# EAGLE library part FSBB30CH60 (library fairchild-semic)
Smart Power Module 600V-30A IGBT inverter for three-phase DC/AC power conversion Source: http://www.fairchildsemi.com/ds/FS/FSBB30CH60.pdf
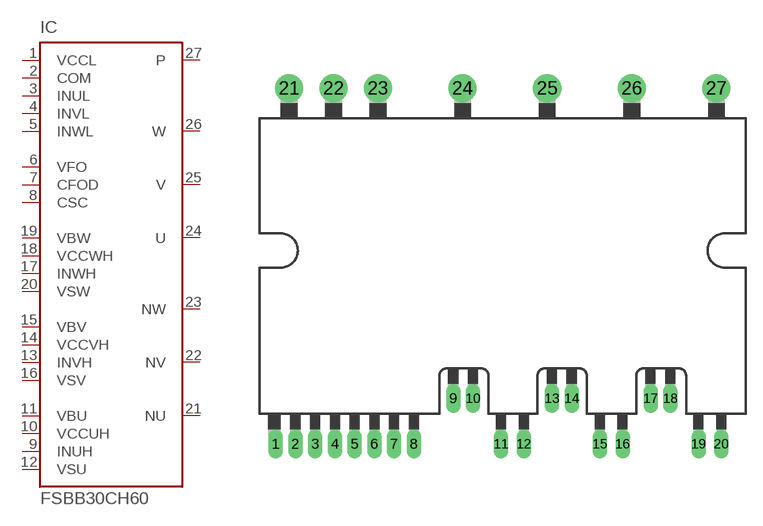
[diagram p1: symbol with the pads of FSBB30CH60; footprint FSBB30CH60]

Designator prefix IC

## FSBB30CH60 (MPN: FSBB30CH60B; OC_FARNELL: 1783234; OC_NEWARK: 78M1076)  [FSBB30CH60]
1  VCCL  pwr
2  COM  pwr
3  INUL  in
4  INVL  in
5  INWL  in
6  VFO  out
7  CFOD  pas
8  CSC  pas
9  INUH  in
10  VCCUH  in
11  VBU  in
12  VSU  in
13  INVH  in
14  VCCVH  in
15  VBV  in
16  VSV  in
17  INWH  in
18  VCCWH  in
19  VBW  in
20  VSW  in
21  NU  in
22  NV  in
23  NW  in
24  U  out
25  V  out
26  W  out
27  P  in

## Footprint FSBB30CH60 (pad centres in mm)
SPM27-EA UL Certified No.E209204 Source: http://www.fairchildsemi.com/ds/FS/FSBB30CH60.pdf
drill 0.8 pad 1.27 long: 1 -20.447,-16; 2 -18.669,-16; 3 -16.891,-16; 4 -15.113,-16; 5 -13.335,-16; 6 -11.557,-16; 7 -9.779,-16; 8 -8.001,-16; 9 -4.445,-11.9; 10 -2.667,-11.9; 11 -0.136,-16; 12 1.914,-16; 13 4.445,-11.9; 14 6.223,-11.9; 15 8.754,-16; 16 10.804,-16; 17 13.335,-11.9; 18 15.113,-11.9; 19 17.644,-16; 20 19.694,-16
drill 1.5 pad 2.54 round: 21 -19.24,16; 22 -15.24,16; 23 -11.24,16; 24 -3.62,16; 25 4,16; 26 11.62,16; 27 19.24,16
